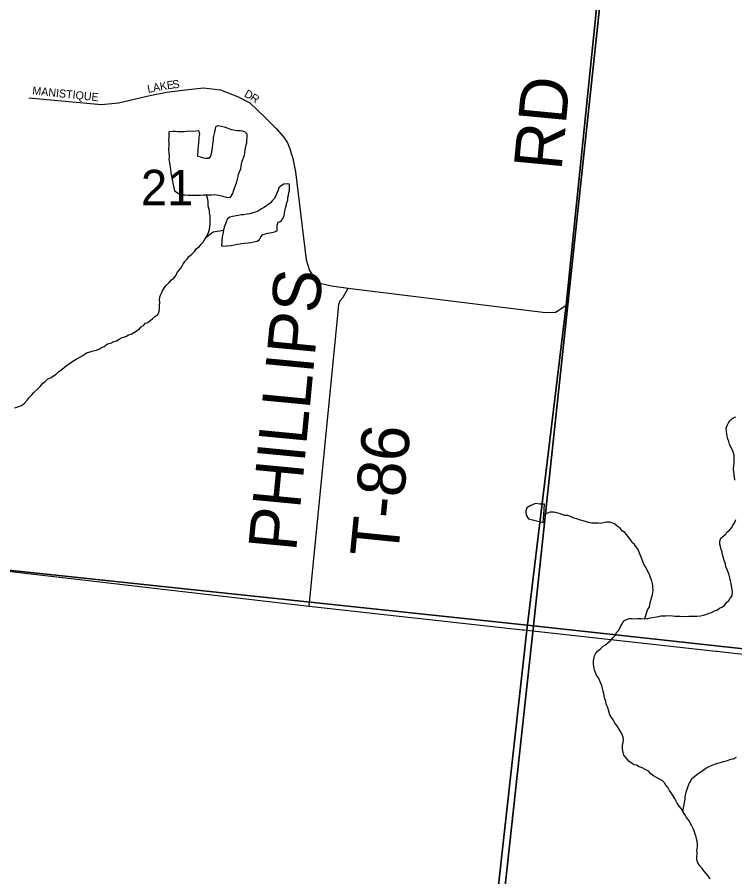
# Model space of a CAD drawing. Extents: x 0 to 34, y -4 to 22.
# Drawn here: x 7.398 to 7.996, y 18.278 to 18.994 of the extents above; entities that cross this region are included whole.
import ezdxf

# ---------------------------------------------------------------- set-up
doc = ezdxf.new("R2010")
doc.units = 0
for name, color, linetype in [('GM_X_Minor_Lake', 7, 'Continuous'), ('GM_X_Minor_River', 7, 'Continuous'), ('GM_X_Section', 7, 'Continuous'), ('GM_X_Section_Text', 7, 'Continuous'), ('GM_X_Township', 7, 'Continuous'), ('GM_X_Township_Road', 7, 'Continuous'), ('GM_X_Township_Road_Text', 7, 'Continuous'), ('GM_X_Township_Subdivision', 7, 'Continuous'), ('GM_X_Township_Subdivision_Text', 7, 'Continuous')]:
    doc.layers.add(name, color=color, linetype=linetype)

msp = doc.modelspace()

# ---------------------------------------------------------------- linework, layer by layer
at = {"layer": 'GM_X_Minor_Lake'}
for points in [[(7.5561, 18.84594), (7.5603, 18.84608), (7.56298, 18.84626), (7.56751, 18.84559), (7.56964, 18.84499), (7.57335, 18.84381), (7.57603, 18.84399), (7.57801, 18.84714), (7.57862, 18.84925), (7.5795, 18.85163), (7.58037, 18.85374), (7.58128, 18.85692), (7.5825, 18.86142), (7.58283, 18.86328), (7.58459, 18.86777), (7.58526, 18.87175), (7.58587, 18.87414), (7.58765, 18.87916), (7.58833, 18.88368), (7.58896, 18.8866), (7.58959, 18.88925), (7.58966, 18.89139), (7.59001, 18.89405), (7.5901, 18.89672), (7.58802, 18.89865), (7.58616, 18.89898), (7.58429, 18.8993), (7.58188, 18.89937), (7.57975, 18.89971), (7.57736, 18.90032), (7.5755, 18.90091), (7.57285, 18.90179), (7.571, 18.90238), (7.56861, 18.90299), (7.56568, 18.90361), (7.5635, 18.90261), (7.56314, 18.89968), (7.56252, 18.8973), (7.56161, 18.89386), (7.56155, 18.89199), (7.56115, 18.88799), (7.56081, 18.88587), (7.56043, 18.88267), (7.56011, 18.88081), (7.55948, 18.87816), (7.55808, 18.87633), (7.55567, 18.87641), (7.55381, 18.87673), (7.55142, 18.87734), (7.54876, 18.87796), (7.54882, 18.87982), (7.54915, 18.88168), (7.54922, 18.88382), (7.54958, 18.88648), (7.54967, 18.88942), (7.55005, 18.89261), (7.55011, 18.89448), (7.55045, 18.89661), (7.54973, 18.8993), (7.54731, 18.89911), (7.54516, 18.89891), (7.54275, 18.89898), (7.53953, 18.89881), (7.53738, 18.89861), (7.53443, 18.89844), (7.53229, 18.8985), (7.53016, 18.89883), (7.52802, 18.8989), (7.52479, 18.89847), (7.5247, 18.8958), (7.52462, 18.8934), (7.52455, 18.89126), (7.52476, 18.88938), (7.52469, 18.88752), (7.52456, 18.88351), (7.52476, 18.88137), (7.52489, 18.87736), (7.52482, 18.87522), (7.52529, 18.87307), (7.52549, 18.8712), (7.5257, 18.86932), (7.52636, 18.86502), (7.52656, 18.86288), (7.52749, 18.85858), (7.52794, 18.85589), (7.52888, 18.85212), (7.52933, 18.84944)], [(7.56854, 18.80362), (7.5704, 18.80329), (7.57282, 18.80348), (7.57659, 18.8039), (7.57928, 18.80435), (7.58521, 18.8055), (7.5879, 18.80569), (7.59086, 18.80613), (7.59301, 18.80633), (7.59543, 18.80679), (7.5984, 18.8075), (7.60032, 18.80878), (7.60147, 18.81115), (7.60314, 18.81297), (7.60531, 18.8137), (7.6072, 18.81418), (7.61043, 18.81461), (7.61286, 18.81534), (7.61503, 18.81607), (7.61511, 18.81847), (7.61492, 18.82088), (7.6158, 18.82326), (7.61825, 18.82425), (7.61966, 18.82635), (7.62081, 18.82872), (7.62114, 18.83058), (7.62147, 18.8327), (7.62182, 18.8351), (7.62242, 18.83695), (7.62304, 18.8396), (7.62391, 18.84171), (7.62399, 18.84384), (7.62431, 18.8457), (7.62466, 18.8481), (7.62526, 18.84995), (7.62534, 18.85235), (7.62516, 18.85503), (7.62329, 18.85535), (7.6206, 18.8549), (7.61841, 18.85363), (7.61648, 18.85182), (7.61588, 18.84997), (7.61472, 18.84734), (7.61357, 18.8447), (7.61243, 18.84287), (7.61077, 18.84105), (7.6091, 18.83923), (7.60443, 18.8359), (7.60197, 18.83437), (7.59951, 18.83285), (7.59706, 18.83159), (7.59463, 18.83113), (7.59219, 18.83013), (7.59004, 18.82993), (7.58708, 18.82949), (7.58493, 18.82929), (7.5825, 18.82883), (7.57765, 18.82791), (7.57549, 18.82744), (7.57357, 18.82617), (7.57271, 18.82432), (7.57182, 18.82195), (7.57092, 18.81904), (7.57036, 18.81664)], [(7.52933, 18.84944), (7.53405, 18.84636), (7.53591, 18.84603), (7.53806, 18.84596), (7.54073, 18.84588), (7.54341, 18.8458), (7.54716, 18.84568), (7.55118, 18.84583), (7.5536, 18.84602), (7.5561, 18.84594)], [(7.57036, 18.81664), (7.56966, 18.8132), (7.56905, 18.81108), (7.56854, 18.80362)]]:
    msp.add_lwpolyline(points, dxfattribs=at)
at = {"layer": 'GM_X_Minor_River'}
for points in [[(7.54393, 18.79663), (7.54615, 18.79896), (7.54783, 18.80132), (7.55003, 18.80285), (7.5517, 18.80494), (7.55337, 18.80676), (7.5545, 18.80859), (7.55591, 18.81069), (7.55705, 18.81279), (7.55765, 18.81464), (7.55854, 18.81728), (7.55889, 18.81968), (7.55924, 18.82207), (7.5593, 18.82394), (7.55911, 18.82635), (7.55919, 18.82875), (7.55873, 18.83117), (7.55853, 18.83304), (7.5578, 18.83547), (7.55761, 18.83788), (7.55743, 18.84029), (7.55722, 18.84217), (7.5561, 18.84594)], [(7.55591, 18.81069), (7.56169, 18.81531), (7.57036, 18.81664)], [(7.39637, 18.66868), (7.4007, 18.67015), (7.4026, 18.6709), (7.40453, 18.67244), (7.40704, 18.6753), (7.40871, 18.67739), (7.41038, 18.6792), (7.41233, 18.68155), (7.41536, 18.68413), (7.41759, 18.68646), (7.41981, 18.68906), (7.42174, 18.69061), (7.42368, 18.69242), (7.42667, 18.69393), (7.42859, 18.69521), (7.43078, 18.69674), (7.43272, 18.69855), (7.43547, 18.7006), (7.43767, 18.70241), (7.44014, 18.7042), (7.44289, 18.70625), (7.4448, 18.70753), (7.44753, 18.70905), (7.45054, 18.71082), (7.453, 18.71235), (7.45602, 18.71439), (7.45926, 18.71536), (7.4617, 18.71609), (7.4644, 18.71681), (7.46684, 18.7178), (7.46875, 18.71881), (7.47093, 18.71981), (7.47368, 18.72186), (7.47638, 18.72258), (7.47883, 18.72384), (7.481, 18.72458), (7.48345, 18.72584), (7.48591, 18.7271), (7.48888, 18.72807), (7.49107, 18.72934), (7.49324, 18.73007), (7.49623, 18.73158), (7.49843, 18.73312), (7.50035, 18.7344), (7.50175, 18.73622), (7.50365, 18.73723), (7.50532, 18.73905), (7.50722, 18.73979), (7.50915, 18.74134), (7.51107, 18.74288), (7.51301, 18.74469), (7.51548, 18.74648), (7.51663, 18.74885), (7.51698, 18.75125), (7.51706, 18.75392), (7.51715, 18.75632), (7.51697, 18.75899), (7.5176, 18.76191), (7.51848, 18.76429), (7.51934, 18.76613), (7.52104, 18.76875), (7.52271, 18.77084), (7.52493, 18.77291), (7.52688, 18.77525), (7.52881, 18.77679), (7.53076, 18.77914), (7.53163, 18.78125), (7.53359, 18.78359), (7.53526, 18.78568), (7.53641, 18.78805), (7.5381, 18.7904), (7.54004, 18.79248), (7.54146, 18.79484), (7.54393, 18.79663)], [(7.99637, 18.60848), (7.99618, 18.61089), (7.99572, 18.61304), (7.99554, 18.61572), (7.99533, 18.6176), (7.99543, 18.62053), (7.99576, 18.62239), (7.99583, 18.62453), (7.99589, 18.6264), (7.99572, 18.62934), (7.99501, 18.63203), (7.994, 18.63393), (7.99274, 18.63638), (7.992, 18.63827), (7.99127, 18.6407), (7.99054, 18.64286), (7.99008, 18.64501), (7.9896, 18.64689), (7.98941, 18.64904), (7.98923, 18.65171), (7.98983, 18.65383), (7.99098, 18.6562), (7.99211, 18.65804), (7.99487, 18.66035), (7.9973, 18.66108)], [(7.82309, 18.58528), (7.82223, 18.5829), (7.82241, 18.57915), (7.82448, 18.57616), (7.83673, 18.57319)], [(7.83712, 18.57988), (7.83763, 18.58841), (7.83388, 18.5885), (7.83014, 18.58886), (7.82636, 18.58734), (7.82309, 18.58528)], [(7.83673, 18.57319), (7.83712, 18.57988)], [(7.92129, 18.49299), (7.92368, 18.5004), (7.9251, 18.50276), (7.92543, 18.50462), (7.92605, 18.50727), (7.92665, 18.50939), (7.92725, 18.51124), (7.92785, 18.51309), (7.92823, 18.51655), (7.92808, 18.52003), (7.92761, 18.52218), (7.92716, 18.5246), (7.92642, 18.52649), (7.92518, 18.52974), (7.92393, 18.53218), (7.92243, 18.53543), (7.9209, 18.53788), (7.91989, 18.53979), (7.91892, 18.54275), (7.91767, 18.54573), (7.91693, 18.54762), (7.91569, 18.5506), (7.91416, 18.55278), (7.91261, 18.5547), (7.91079, 18.55636), (7.90979, 18.55853), (7.90748, 18.56154), (7.90464, 18.56483), (7.90255, 18.56623), (7.90074, 18.56843), (7.89839, 18.5701), (7.89604, 18.57204), (7.89393, 18.57291), (7.89207, 18.5735), (7.88938, 18.57332), (7.88669, 18.57287), (7.88453, 18.5724), (7.88266, 18.57246), (7.87945, 18.57256), (7.87704, 18.57263), (7.87438, 18.57325), (7.87199, 18.57386), (7.8688, 18.57476), (7.86668, 18.57536), (7.86457, 18.57622), (7.86217, 18.57683), (7.85953, 18.57798), (7.85715, 18.57886), (7.85474, 18.57893), (7.85289, 18.57952), (7.85104, 18.58038), (7.84892, 18.58098), (7.84678, 18.58141), (7.84511, 18.58163), (7.84254, 18.58163), (7.83712, 18.57988)], [(7.99089, 18.53172), (7.98964, 18.53443), (7.9889, 18.53658), (7.98844, 18.53874), (7.98746, 18.54144), (7.98675, 18.5444), (7.98601, 18.54629), (7.98581, 18.54843), (7.98508, 18.55059), (7.98436, 18.55302), (7.98389, 18.55517), (7.98397, 18.55757), (7.98459, 18.55996), (7.98652, 18.56177), (7.98872, 18.5633), (7.98958, 18.56515), (7.99177, 18.56668), (7.99373, 18.56903), (7.99459, 18.57087), (7.99599, 18.5727), (7.99716, 18.5756)], [(7.91906, 18.36884), (7.91668, 18.36972), (7.91431, 18.37086), (7.91244, 18.37118), (7.91009, 18.37286), (7.90799, 18.37426), (7.90567, 18.377), (7.90387, 18.3792), (7.90341, 18.38161), (7.9027, 18.38431), (7.90276, 18.38618), (7.90282, 18.38804), (7.90342, 18.3899), (7.9035, 18.3923), (7.90329, 18.39417), (7.90257, 18.3966), (7.90104, 18.39905), (7.89952, 18.40177), (7.89799, 18.40395), (7.89644, 18.40587), (7.89493, 18.40886), (7.89366, 18.41077), (7.89212, 18.41295), (7.89142, 18.41591), (7.89043, 18.41861), (7.88921, 18.42212), (7.88875, 18.42427), (7.88801, 18.42617), (7.88756, 18.42885), (7.88708, 18.43074), (7.88661, 18.43262), (7.88615, 18.43477), (7.88543, 18.43747), (7.88444, 18.4399), (7.88269, 18.4437), (7.88115, 18.44588), (7.88015, 18.44805), (7.87942, 18.45021), (7.87872, 18.45317), (7.87853, 18.45558), (7.8786, 18.45771), (7.87893, 18.45957), (7.87954, 18.46196), (7.88014, 18.46381), (7.88182, 18.4659), (7.88429, 18.46796), (7.88651, 18.47002), (7.88869, 18.47129), (7.89062, 18.47284), (7.89283, 18.4749), (7.89477, 18.47698), (7.89672, 18.47906), (7.89787, 18.48143), (7.89927, 18.48326), (7.9004, 18.48509), (7.90127, 18.48693), (7.9024, 18.48877), (7.90381, 18.49113), (7.906, 18.4924), (7.90817, 18.49313), (7.91084, 18.49305), (7.91299, 18.49298), (7.9154, 18.49317), (7.91835, 18.49308), (7.92129, 18.49299), (7.92398, 18.49318), (7.92587, 18.49365), (7.92937, 18.49435), (7.9326, 18.49478), (7.93476, 18.49525), (7.93852, 18.4954), (7.94147, 18.49557), (7.94441, 18.49548), (7.94628, 18.49516), (7.94842, 18.49509), (7.95083, 18.49502), (7.95404, 18.49492), (7.95806, 18.49506), (7.96127, 18.49496), (7.96476, 18.49512), (7.96771, 18.4953), (7.97015, 18.49602), (7.97312, 18.49674), (7.97502, 18.49748), (7.97692, 18.49822), (7.97937, 18.49948), (7.98127, 18.50022), (7.98347, 18.50176), (7.98537, 18.5025), (7.98783, 18.50403), (7.98924, 18.50612), (7.99145, 18.50819), (7.99258, 18.51002), (7.99399, 18.51212), (7.99437, 18.51558), (7.99394, 18.5188), (7.99325, 18.52229), (7.99279, 18.52444), (7.99207, 18.52714), (7.99161, 18.52929), (7.99089, 18.53172)], [(7.95295, 18.33226), (7.9549, 18.34262), (7.95496, 18.34449), (7.9559, 18.34847), (7.95651, 18.35086), (7.9574, 18.3535), (7.95828, 18.35561), (7.95941, 18.35744), (7.96056, 18.35981), (7.96276, 18.36162), (7.96496, 18.36342), (7.96798, 18.36546), (7.9699, 18.36674), (7.9721, 18.36854), (7.97509, 18.36978), (7.97754, 18.37104), (7.98025, 18.37203), (7.98323, 18.373), (7.98512, 18.37348), (7.98701, 18.37396), (7.99026, 18.37492), (7.99297, 18.37591), (7.99513, 18.37638), (7.99785, 18.37763)], [(7.97575, 18.27626), (7.97422, 18.27872), (7.97241, 18.28064), (7.97061, 18.28283), (7.96907, 18.28502), (7.96701, 18.28749), (7.96547, 18.28967), (7.96475, 18.2921), (7.96457, 18.29477), (7.9649, 18.29663), (7.96496, 18.2985), (7.96476, 18.30038), (7.9651, 18.30277), (7.96518, 18.30517), (7.96499, 18.30758), (7.96452, 18.30947), (7.96405, 18.31135), (7.96332, 18.31351), (7.96233, 18.31622), (7.96159, 18.31811), (7.9606, 18.32054), (7.95882, 18.32354), (7.95781, 18.32544), (7.956, 18.32736), (7.95475, 18.32981), (7.95295, 18.33226), (7.9517, 18.33498), (7.94989, 18.3369), (7.94836, 18.33935), (7.94709, 18.34153), (7.94609, 18.34343), (7.9443, 18.34616), (7.94329, 18.34806), (7.94202, 18.34997), (7.94075, 18.35214), (7.93894, 18.35434), (7.93767, 18.35625), (7.93586, 18.35817), (7.93348, 18.35931), (7.93112, 18.36072), (7.92849, 18.36214), (7.9264, 18.36381), (7.92433, 18.36601), (7.92169, 18.36742), (7.91906, 18.36884)]]:
    msp.add_lwpolyline(points, dxfattribs=at)
at = {"layer": 'GM_X_Section'}
for points in [[(7.90105, 19.1654), (7.82864, 18.48717), (7.15014, 18.55903), (7.21731, 19.22831)], [(7.90105, 19.1654), (8.59171, 19.1029), (8.52385, 18.41099), (7.82864, 18.48717)], [(7.15014, 18.55903), (7.82864, 18.48717), (7.74884, 17.75662), (7.07455, 17.825)], [(7.82864, 18.48717), (8.52385, 18.41099), (8.46166, 17.69579), (7.74884, 17.75662)]]:
    msp.add_lwpolyline(points, close=True, dxfattribs=at)
at = {"layer": 'GM_X_Township'}
for points in [[(7.70395, 17.41086), (7.82296, 18.48336), (7.8558, 18.75422), (7.89749, 19.16191), (6.95864, 19.25607)], [(8.9, 14.99227), (8.9, 19.07101), (8.74356, 19.08501), (8.61662, 19.09679), (7.89749, 19.16191), (7.8558, 18.75422), (7.82296, 18.48336), (7.70395, 17.41086)]]:
    msp.add_lwpolyline(points, dxfattribs=at)
at = {"layer": 'GM_X_Township_Road'}
for points in [[(7.84963, 18.75008), (7.85133, 18.75122), (7.8558, 18.75422), (7.89749, 19.16191)], [(7.64163, 18.50332), (7.66574, 18.74859), (7.66639, 18.75501), (7.66779, 18.75846), (7.66998, 18.76083), (7.67429, 18.76821), (7.83855, 18.74809), (7.84686, 18.74822), (7.84963, 18.75008)], [(7.35225, 18.53711), (7.64163, 18.50332), (7.81945, 18.48375), (7.82068, 18.48361)], [(7.82068, 18.48361), (7.82296, 18.48336), (7.98046, 18.46602), (7.98156, 18.4659)], [(7.98156, 18.4659), (7.98607, 18.4654), (8.23528, 18.43711), (8.52009, 18.40608)]]:
    msp.add_lwpolyline(points, dxfattribs=at)
at = {"layer": 'GM_X_Township_Subdivision'}
msp.add_lwpolyline([(7.40813, 18.92699), (7.46871, 18.92128), (7.48273, 18.92277), (7.50893, 18.92873), (7.52308, 18.93146), (7.5386, 18.93345), (7.55374, 18.93518), (7.56777, 18.93345), (7.58192, 18.92798), (7.5921, 18.92265), (7.60452, 18.91097), (7.61408, 18.90129), (7.62041, 18.89447), (7.62363, 18.8895), (7.62562, 18.88429), (7.6281, 18.87621), (7.63034, 18.86529), (7.63903, 18.79205), (7.64201, 18.78311), (7.64821, 18.77293), (7.66038, 18.7702), (7.67429, 18.76821)], dxfattribs=at)

# ---------------------------------------------------------------- texts
at = {"layer": 'GM_X_Section_Text'}
msp.add_text('21', height=0.029444, rotation=0.00001, dxfattribs=at).set_placement((7.50144, 18.83745))
at = {"layer": 'GM_X_Township_Road_Text'}
for s, rotation, p in [('RD', 84.58411, (7.85186, 18.86566)), ('PHILLIPS', 84.52912, (7.63068, 18.54829)), ('T-86', 84.32368, (7.71543, 18.54285))]:
    msp.add_text(s, height=0.04, rotation=rotation, dxfattribs=at).set_placement(p)
at = {"layer": 'GM_X_Township_Subdivision_Text'}
for s, height, rotation, p in [('K', 0.00667, 10.0409, (7.51782, 18.9329)), ('E', 0.00667, 8.47402, (7.52354, 18.93391)), ('S', 0.00667, 7.92144, (7.52817, 18.9346)), ('MANISTIQUE', 0.006667, 354.02407, (7.41074, 18.92977)), ('L', 0.00667, 10.82775, (7.50747, 18.93092)), ('A', 0.00667, 10.8338, (7.51208, 18.9318)), ('D', 0.00667, 330.71608, (7.58697, 18.92833)), ('R', 0.00667, 325.27259, (7.59194, 18.92555))]:
    msp.add_text(s, height=height, rotation=rotation, dxfattribs=at).set_placement(p)

doc.saveas('drawing.dxf')
